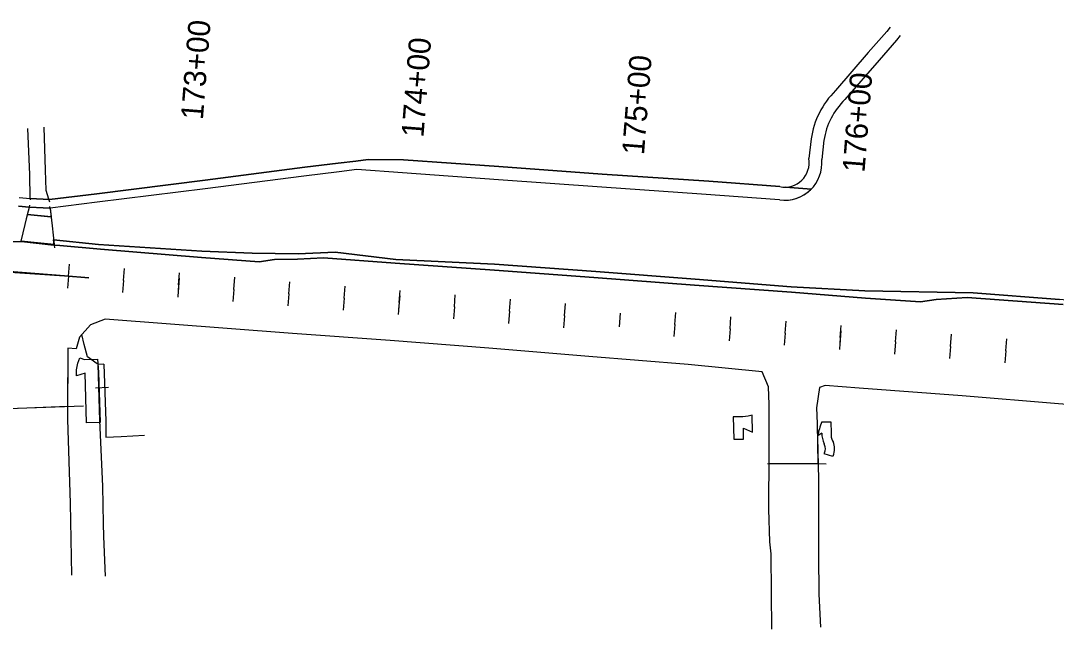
# Model space of a CAD drawing. Extents: x 20499880 to 20505309, y 7953507 to 7955507.
# Drawn here: x 20500939.7 to 20501407.8, y 7953800.6 to 7954075.5 of the extents above; entities that cross this region are included whole.
import ezdxf

# ---------------------------------------------------------------- set-up
doc = ezdxf.new("R2010")
doc.units = 0
for name, color, linetype in [('Alignment', 7, 'Continuous'), ('Curb', 7, 'Continuous'), ('Draft_0', 7, 'Continuous'), ('Entrance', 7, 'Continuous')]:
    doc.layers.add(name, color=color, linetype=linetype)

msp = doc.modelspace()

# ---------------------------------------------------------------- linework, layer by layer
at = {"layer": 'Alignment'}
for p, q in [((20501011.07, 7953956.16), (20501011.5, 7953961.6)), ((20501011.07, 7953956.16), (20501010.64, 7953950.71)), ((20501110.76, 7953948.24), (20501111.19, 7953953.68)), ((20501110.76, 7953948.24), (20501110.32, 7953942.79)), ((20501210.69, 7953943.36), (20501210.2, 7953937.26)), ((20501210.69, 7953943.36), (20501210.2, 7953937.26)), ((20501310.13, 7953932.39), (20501310.56, 7953937.83)), ((20501310.13, 7953932.39), (20501309.7, 7953926.95))]:
    msp.add_line(p, q, dxfattribs=at)
at = {"layer": 'Curb'}
for p, q in [((20501332.71, 7954072.58), (20501331.19, 7954070.67)), ((20501331.19, 7954070.67), (20501322.77, 7954061.14)), ((20501335.48, 7954066.77), (20501327.68, 7954057.74)), ((20501337.22, 7954068.85), (20501335.48, 7954066.77)), ((20501322.77, 7954061.14), (20501307.99, 7954043.95)), ((20501327.68, 7954057.74), (20501312.24, 7954039.94)), ((20501296.95, 7954022.19), (20501295.83, 7954013.28)), ((20501302.7, 7954021.51), (20501301.78, 7954012.84)), ((20501083.14, 7954011.14), (20501068.12, 7954009.31)), ((20501091.1, 7954012.12), (20501083.14, 7954011.14)), ((20501096.79, 7954012.86), (20501091.1, 7954012.12)), ((20501112.72, 7954012.7), (20501096.79, 7954012.86)), ((20501155.79, 7954009.63), (20501112.72, 7954012.7)), ((20501068.12, 7954009.31), (20501023, 7954003.54)), ((20501083.64, 7954007.27), (20501067.66, 7954005.34)), ((20501091.58, 7954008.39), (20501083.64, 7954007.27)), ((20501112.28, 7954006.84), (20501091.58, 7954008.39)), ((20501155.71, 7954003.73), (20501112.28, 7954006.84)), ((20501202.53, 7954006.24), (20501155.79, 7954009.63)), ((20501250.66, 7954003.04), (20501202.53, 7954006.24)), ((20501023, 7954003.54), (20500974.05, 7953997.33)), ((20501067.66, 7954005.34), (20501022.98, 7953999.61)), ((20501202.3, 7954000.41), (20501155.71, 7954003.73)), ((20501282.84, 7954000.6), (20501250.66, 7954003.04)), ((20500974.05, 7953997.33), (20500952.76, 7953994.71)), ((20501022.98, 7953999.61), (20500974.3, 7953993.5)), ((20501247.32, 7953997.2), (20501202.3, 7954000.41)), ((20501282.72, 7953994.59), (20501247.32, 7953997.2)), ((20501297.04, 7953999.51), (20501285.4, 7954000.36)), ((20500943.61, 7953991.27), (20500943.82, 7953992.16)), ((20500952.76, 7953994.71), (20500943.94, 7953995.2)), ((20500943.99, 7953995.33), (20500944, 7953994.69)), ((20500952.31, 7953995.08), (20500952.76, 7953993.71)), ((20500953.01, 7953990.63), (20500952.91, 7953991.54)), ((20500974.3, 7953993.5), (20500952.98, 7953990.8)), ((20500952.98, 7953990.8), (20500943.48, 7953991.35)), ((20500979.35, 7953909.78), (20500973.44, 7953909.58)), ((20500968.09, 7953901.45), (20500933.95, 7953900.26)), ((20501277.24, 7953875.53), (20501303.69, 7953875.32))]:
    msp.add_line(p, q, dxfattribs=at)
for points in [[(20500943.99, 7953995.33), (20500943.83, 7954006.13), (20500942.97, 7954026.78)], [(20500950.17, 7954027.5), (20500950.79, 7954007.97), (20500951, 7953999.06), (20500952.31, 7953995.08)], [(20500938.72, 7953991.76), (20500943.48, 7953991.35)], [(20500939.01, 7953995.67), (20500943.94, 7953995.2)], [(20500953.01, 7953990.63), (20500953.89, 7953982.84), (20500954.73, 7953974.52), (20500947.32, 7953975.21), (20500939.94, 7953976), (20500941.73, 7953983.49), (20500943.61, 7953991.27)], [(20501410.85, 7953947.34), (20501367.41, 7953950.44), (20501353.47, 7953949.58), (20501346.41, 7953948.6), (20501321.54, 7953950.25), (20501288.12, 7953952.88), (20501244.22, 7953956.13), (20501198.7, 7953959.48), (20501153.78, 7953962.79), (20501108.92, 7953966.07), (20501076.54, 7953968.42), (20501064.8, 7953967.85), (20501054.38, 7953967.6), (20501047.51, 7953966.59), (20501021.32, 7953968.6), (20500975.73, 7953972.3), (20500957.39, 7953974.04), (20500954.64, 7953974.2), (20500940.08, 7953975.84), (20500931.44, 7953975.72)], [(20501653.78, 7953927.23), (20501653.77, 7953927.86), (20501636.16, 7953930.64), (20501589.4, 7953934.88), (20501495.94, 7953942.1), (20501484.96, 7953944.03), (20501455.22, 7953945.39), (20501409.27, 7953949.65), (20501370.2, 7953952.66), (20501321.27, 7953953.59), (20501287.99, 7953955.38), (20501244.51, 7953958.83), (20501199.67, 7953962.27), (20501153.86, 7953965.49), (20501109.17, 7953967.64), (20501081.81, 7953970.91), (20501065.07, 7953970.3), (20501044.25, 7953970.49), (20501021.55, 7953971.51), (20500974.87, 7953974.47), (20500954.52, 7953976.56), (20500954.89, 7953972.95)], [(20501279.18, 7953800.61), (20501279.07, 7953816.88), (20501278.9, 7953834.64), (20501278.24, 7953840.19), (20501277.86, 7953854.9), (20501277.86, 7953865.97), (20501278, 7953868.87), (20501277.92, 7953902.19), (20501277.62, 7953910.12), (20501274.78, 7953916.96), (20501241.29, 7953920.29), (20501196.44, 7953923.91), (20501151.21, 7953927.66), (20501106.6, 7953931.1), (20501062.55, 7953934.28), (20500977.86, 7953940.69), (20500971.17, 7953938.08), (20500966.3, 7953932.53), (20500964.8, 7953927.31), (20500961.01, 7953927.54), (20500960.84, 7953895.35), (20500962.08, 7953857.52), (20500962.69, 7953825.13)], [(20500974.28, 7953920.53), (20500969.8, 7953923.75), (20500968.33, 7953929.33), (20500967.38, 7953933.81)], [(20500977.31, 7953920.39), (20500974.49, 7953920.29), (20500975.36, 7953894.87), (20500976.59, 7953865.28), (20500976.9, 7953848.4), (20500977.12, 7953842.6), (20500977.9, 7953824.67)], [(20500977.31, 7953920.39), (20500978.16, 7953894.69), (20500978.11, 7953887.42), (20500985.13, 7953887.72), (20500995.61, 7953888.26)], [(20501717.61, 7953875.88), (20501671.53, 7953880.18), (20501628.56, 7953883.94), (20501583.34, 7953887.59), (20501537.38, 7953891.4), (20501490.63, 7953895.73), (20501451.22, 7953899.23), (20501408.69, 7953902.39), (20501365.27, 7953906.03), (20501318.62, 7953909.59), (20501303.35, 7953910.68), (20501300.71, 7953909.78), (20501299.38, 7953900.73), (20501299.61, 7953893.51), (20501300.21, 7953868.42), (20501300.22, 7953842.73), (20501300.2, 7953834.08), (20501300.49, 7953816.42), (20501301.22, 7953801.6)]]:
    msp.add_lwpolyline(points, dxfattribs=at)
for centre, major_axis, ratio, start_param, end_param in [((20501334.33, 7954016.93), (-25.19, -28.16), 0.998831, 4.644172, 5.301883), ((20501335, 7954016.48), (-31.66, -8.13), 0.999886, 5.231361, 5.877508), ((20501284.96, 7954011.33), (13.6, -10.02), 0.999468, 5.214503, 7.008267), ((20501285.14, 7954011.25), (-4.47, 9.94), 0.99878, 2.505758, 4.476928)]:
    msp.add_ellipse(centre, major_axis=major_axis, ratio=ratio, start_param=start_param, end_param=end_param, dxfattribs=at)
at = {"layer": 'Draft_0'}
for p, q in [((20501285.4, 7954000.36), (20501297.04, 7953999.51)), ((20501301.71, 7953889.21), (20501299.93, 7953887.94)), ((20501303.01, 7953883.99), (20501302.82, 7953884.46)), ((20501306.68, 7953885.72), (20501306.87, 7953885.38))]:
    msp.add_line(p, q, dxfattribs=at)
for points in [[(20500939.01, 7953995.67), (20500943.94, 7953995.2), (20500952.76, 7953994.71), (20500974.05, 7953997.33), (20501023, 7954003.54), (20501068.12, 7954009.31), (20501083.14, 7954011.14), (20501091.1, 7954012.12), (20501096.79, 7954012.86), (20501112.72, 7954012.7), (20501155.79, 7954009.63), (20501202.53, 7954006.24), (20501250.66, 7954003.04), (20501282.84, 7954000.6)], [(20501282.72, 7953994.59), (20501247.32, 7953997.2), (20501202.3, 7954000.41), (20501155.71, 7954003.73), (20501112.28, 7954006.84), (20501091.58, 7954008.39), (20501083.64, 7954007.27), (20501067.66, 7954005.34), (20501022.98, 7953999.61), (20500974.3, 7953993.5), (20500952.98, 7953990.8), (20500943.48, 7953991.35), (20500938.72, 7953991.76)], [(20500931.44, 7953975.72), (20500940.08, 7953975.84), (20500954.64, 7953974.2), (20500957.39, 7953974.04), (20500975.73, 7953972.3), (20501021.32, 7953968.6), (20501047.51, 7953966.59), (20501054.38, 7953967.6), (20501064.8, 7953967.85), (20501076.54, 7953968.42), (20501108.92, 7953966.07), (20501153.78, 7953962.79), (20501198.7, 7953959.48), (20501244.22, 7953956.13), (20501288.12, 7953952.88), (20501321.54, 7953950.25), (20501346.41, 7953948.6), (20501353.47, 7953949.58), (20501367.41, 7953950.44), (20501410.85, 7953947.34)], [(20501410.85, 7953947.34), (20501367.41, 7953950.44), (20501353.47, 7953949.58), (20501346.41, 7953948.6), (20501321.54, 7953950.25), (20501288.12, 7953952.88), (20501244.22, 7953956.13), (20501198.7, 7953959.48), (20501153.78, 7953962.79), (20501108.92, 7953966.07), (20501076.54, 7953968.42), (20501064.8, 7953967.85), (20501054.38, 7953967.6), (20501047.51, 7953966.59), (20501021.32, 7953968.6), (20500975.73, 7953972.3), (20500957.39, 7953974.04), (20500954.76, 7953974.19), (20500954.52, 7953976.56), (20500974.87, 7953974.47), (20501021.55, 7953971.51), (20501044.25, 7953970.49), (20501065.07, 7953970.3), (20501081.81, 7953970.91), (20501109.17, 7953967.64), (20501153.86, 7953965.49), (20501199.67, 7953962.27), (20501244.51, 7953958.83), (20501287.99, 7953955.38), (20501321.27, 7953953.59), (20501370.2, 7953952.66), (20501409.27, 7953949.65)], [(20500930.1, 7953962.26), (20500948.33, 7953961.08), (20500959.52, 7953960.25), (20500970.49, 7953959.38), (20500970.5, 7953959.44), (20500959.52, 7953960.25), (20500907.68, 7953964.37)], [(20501408.69, 7953902.39), (20501365.27, 7953906.03), (20501318.62, 7953909.59), (20501303.35, 7953910.68), (20501300.71, 7953909.78), (20501299.38, 7953900.73), (20501299.61, 7953893.51), (20501300.04, 7953875.35), (20501277.98, 7953875.53), (20501277.92, 7953902.19), (20501277.62, 7953910.12), (20501274.78, 7953916.96), (20501241.29, 7953920.29), (20501196.44, 7953923.91), (20501151.21, 7953927.66), (20501106.6, 7953931.1), (20501062.55, 7953934.28), (20500977.86, 7953940.69), (20500971.17, 7953938.08), (20500966.3, 7953932.53), (20500964.8, 7953927.31), (20500961.01, 7953927.54), (20500960.87, 7953901.2), (20500938.61, 7953900.42)], [(20501301.82, 7953894.32), (20501305.84, 7953894.26), (20501305.95, 7953889.26)], [(20501306.91, 7953879), (20501306.78, 7953878.61), (20501302.91, 7953879.9), (20501302.91, 7953879.9)]]:
    msp.add_lwpolyline(points, dxfattribs=at)
for points in [[(20500953.89, 7953982.84), (20500954.73, 7953974.52), (20500947.32, 7953975.21), (20500939.94, 7953976), (20500941.73, 7953983.49), (20500942.81, 7953987.97), (20500953.26, 7953987.01), (20500953.46, 7953986.66)], [(20500953.42, 7953987), (20500942.81, 7953987.97), (20500943.63, 7953991.34), (20500952.98, 7953990.8), (20500952.99, 7953990.8)], [(20500968.45, 7953922.53), (20500974.45, 7953922.58), (20500974.88, 7953916.75), (20500975.54, 7953894.02), (20500969.49, 7953893.86), (20500968.8, 7953916.38), (20500964.88, 7953915.14), (20500964.93, 7953917.75), (20500965.51, 7953920.89), (20500966.35, 7953923.31)], [(20501261.93, 7953886.46), (20501266.35, 7953886.51), (20501266.34, 7953891.41), (20501270.43, 7953889.61), (20501270.26, 7953897.3), (20501268.41, 7953896.9), (20501266.12, 7953896.58), (20501261.68, 7953896.52), (20501261.68, 7953896.52)]]:
    msp.add_lwpolyline(points, close=True, dxfattribs=at)
for centre, radius, start, end in [((20501324.03, 7953884.26), 24.37, 155.6292, 171.3291), ((20501301.04, 7953880.61), 2, 339.2009, 350.5889)]:
    msp.add_arc(centre, radius, start, end, dxfattribs=at)
for centre, major_axis, ratio, start_param, end_param in [((20501284.96, 7954011.33), (13.6, -10.02), 0.999468, 5.214503, 6.14421), ((20501285.14, 7954011.25), (-4.47, 9.94), 0.99878, 2.505758, 2.74241), ((20501314.55, 7953889.71), (3.39, -12.43), 0.997333, 4.485561, 4.866099), ((20501312.54, 7953888.78), (-1, -6.54), 0.999209, 4.791232, 5.344404), ((20501299.23, 7953882.13), (-3.61, 2.17), 0.999828, 3.229181, 4.139845), ((20501298.79, 7953882.14), (2.72, 8.27), 0.999549, 4.661245, 5.41162)]:
    msp.add_ellipse(centre, major_axis=major_axis, ratio=ratio, start_param=start_param, end_param=end_param, dxfattribs=at)
at = {"layer": 'Entrance'}
for p, q in [((20500961.23, 7953960.12), (20500961.66, 7953965.56)), ((20500986.15, 7953958.14), (20500986.58, 7953963.58)), ((20500961.23, 7953960.12), (20500960.8, 7953954.68)), ((20501011.31, 7953959.21), (20501010.83, 7953953.11)), ((20501011.31, 7953959.21), (20501010.83, 7953953.11)), ((20501035.99, 7953954.18), (20501036.43, 7953959.62)), ((20500986.15, 7953958.14), (20500985.72, 7953952.69)), ((20501035.99, 7953954.18), (20501035.56, 7953948.73)), ((20501060.91, 7953952.2), (20501061.35, 7953957.64)), ((20501085.84, 7953950.22), (20501086.27, 7953955.66)), ((20501060.91, 7953952.2), (20501060.48, 7953946.75)), ((20501085.84, 7953950.22), (20501085.4, 7953944.77)), ((20501111, 7953951.29), (20501110.51, 7953945.19)), ((20501111, 7953951.29), (20501110.51, 7953945.19)), ((20501135.68, 7953946.26), (20501136.11, 7953951.7)), ((20501160.6, 7953944.27), (20501161.03, 7953949.72)), ((20501135.68, 7953946.26), (20501135.25, 7953940.81)), ((20501185.52, 7953942.29), (20501185.95, 7953947.74)), ((20501160.6, 7953944.27), (20501160.17, 7953938.83)), ((20501185.52, 7953942.29), (20501185.09, 7953936.85)), ((20501210.69, 7953943.36), (20501210.2, 7953937.26)), ((20501210.69, 7953943.36), (20501210.2, 7953937.26)), ((20501235.36, 7953938.33), (20501235.8, 7953943.78)), ((20501260.29, 7953936.35), (20501260.72, 7953941.8)), ((20501235.36, 7953938.33), (20501234.93, 7953932.89)), ((20501260.29, 7953936.35), (20501259.85, 7953930.91)), ((20501285.21, 7953934.37), (20501285.64, 7953939.82)), ((20501310.37, 7953935.44), (20501309.89, 7953929.34)), ((20501310.37, 7953935.44), (20501309.89, 7953929.34)), ((20501335.05, 7953930.41), (20501335.48, 7953935.85)), ((20501285.21, 7953934.37), (20501284.77, 7953928.93)), ((20501359.97, 7953928.43), (20501360.4, 7953933.87)), ((20501384.89, 7953926.45), (20501385.33, 7953931.89)), ((20501335.05, 7953930.41), (20501334.62, 7953924.97)), ((20501359.97, 7953928.43), (20501359.54, 7953922.99)), ((20501384.89, 7953926.45), (20501384.46, 7953921.01))]:
    msp.add_line(p, q, dxfattribs=at)

# ---------------------------------------------------------------- texts
at = {"layer": 'Alignment'}
msp.add_text('175+00', height=10.02, rotation=85.4564, dxfattribs=at).set_placement((20501221.38, 7954014.68))
at = {"layer": 'Entrance'}
for s, p in [('173+00', (20501022.01, 7954030.52)), ('174+00', (20501121.69, 7954022.6)), ('175+00', (20501221.38, 7954014.68)), ('176+00', (20501321.06, 7954006.76))]:
    msp.add_text(s, height=10.02, rotation=85.4564, dxfattribs=at).set_placement(p)

doc.saveas('drawing.dxf')
